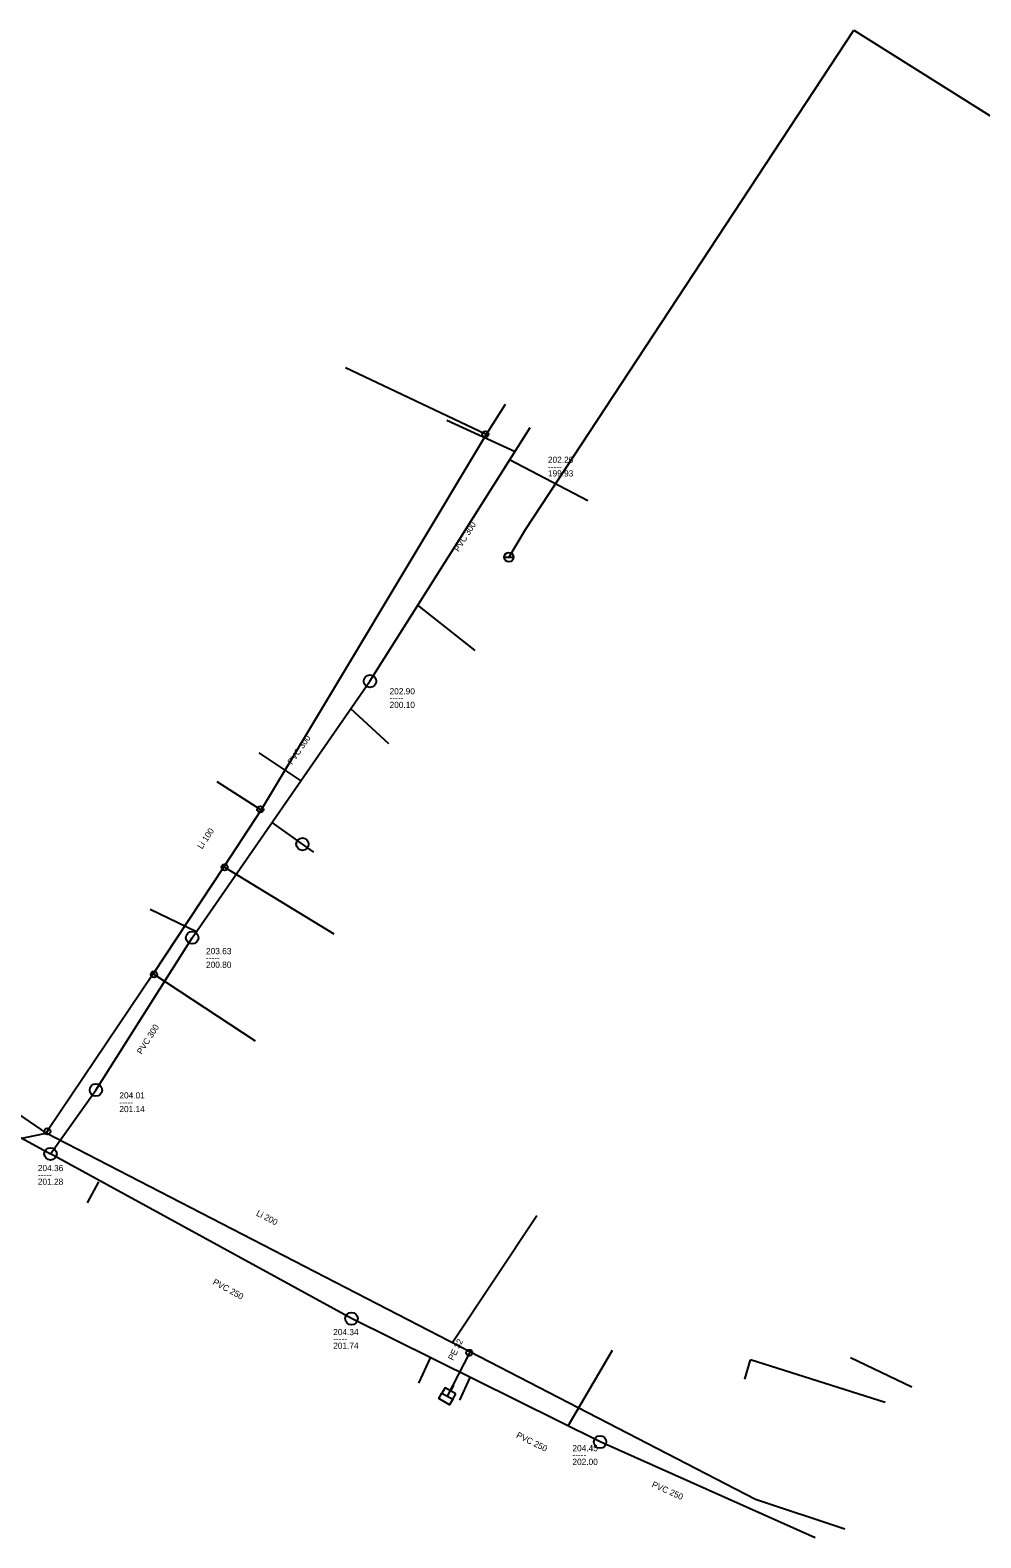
# Model space of a CAD drawing. Extents: x -695225 to -694112, y -1052622 to -1052029.
# Drawn here: x -694820.4 to -694667.2, y -1052494.8 to -1052251.9 of the extents above; entities that cross this region are included whole.
import ezdxf

# ---------------------------------------------------------------- set-up
doc = ezdxf.new("R2010")
doc.units = 0
doc.layers.add('Level 0', color=7, linetype='Continuous')

msp = doc.modelspace()

# ---------------------------------------------------------------- linework, layer by layer
at = {"layer": 'Level 0'}
for p, q in [((-694740.58, -1052332.34), (-694687.67, -1052251.87)), ((-694687.67, -1052251.87), (-694642.99, -1052280.01)), ((-694747.05, -1052316.98), (-694769.59, -1052306.28)), ((-694743.86, -1052312.18), (-694746.91, -1052317.04)), ((-694765.63, -1052356.77), (-694739.83, -1052315.88)), ((-694753.24, -1052314.74), (-694742.27, -1052319.76)), ((-694746.91, -1052317.04), (-694783.16, -1052377.52)), ((-694746.91, -1052317.04), (-694747.05, -1052316.98)), ((-694730.52, -1052327.74), (-694743.14, -1052321.13)), ((-694743.25, -1052336.86), (-694740.58, -1052332.34)), ((-694744, -1052336.8), (-694742.5, -1052336.8)), ((-694748.69, -1052351.82), (-694757.92, -1052344.55)), ((-694794.26, -1052398.11), (-694765.63, -1052356.77)), ((-694762.6, -1052366.87), (-694768.73, -1052361.24)), ((-694783.55, -1052368.32), (-694776.77, -1052372.86)), ((-694790.32, -1052372.96), (-694783.29, -1052377.44)), ((-694783.16, -1052377.52), (-694789.19, -1052386.69)), ((-694783.29, -1052377.44), (-694783.16, -1052377.52)), ((-694776.51, -1052383.04), (-694781.4, -1052379.54)), ((-694774.68, -1052384.34), (-694776.51, -1052383.04)), ((-694789.19, -1052386.69), (-694800.54, -1052403.94)), ((-694789.19, -1052386.69), (-694789.06, -1052386.77)), ((-694789.06, -1052386.77), (-694771.43, -1052397.47)), ((-694801.04, -1052393.49), (-694793.57, -1052397.11)), ((-694809.78, -1052422.66), (-694794.27, -1052398.11)), ((-694861.88, -1052399.44), (-694817.8, -1052429.59)), ((-694800.54, -1052403.94), (-694817.45, -1052429.07)), ((-694800.41, -1052404.02), (-694800.54, -1052403.94)), ((-694784.07, -1052414.79), (-694800.41, -1052404.02)), ((-694817.1, -1052432.95), (-694809.78, -1052422.66)), ((-694827.23, -1052427.44), (-694817.1, -1052432.95)), ((-694828.53, -1052431.86), (-694817.8, -1052429.59)), ((-694817.62, -1052429.32), (-694817.8, -1052429.59)), ((-694749.55, -1052464.87), (-694817.8, -1052429.59)), ((-694817.45, -1052429.07), (-694817.62, -1052429.32)), ((-694768.61, -1052459.5), (-694817.1, -1052432.95)), ((-694811.15, -1052440.82), (-694809.33, -1052437.46)), ((-694752.38, -1052463.41), (-694738.78, -1052442.87)), ((-694728.57, -1052479.37), (-694768.61, -1052459.5)), ((-694757.75, -1052469.88), (-694755.88, -1052465.82)), ((-694749.62, -1052465), (-694753.18, -1052472)), ((-694749.55, -1052464.87), (-694749.62, -1052465)), ((-694703.52, -1052488.66), (-694749.55, -1052464.87)), ((-694726.64, -1052464.65), (-694733.75, -1052476.8)), ((-694705.25, -1052469.23), (-694704.36, -1052466.15)), ((-694682.66, -1052473.03), (-694704.36, -1052466.15)), ((-694688.24, -1052465.76), (-694678.36, -1052470.5)), ((-694751.18, -1052472.66), (-694749.51, -1052468.97)), ((-694752.18, -1052470.26795), (-694752.68, -1052471.13397)), ((-694693.94, -1052494.82), (-694728.57, -1052479.37)), ((-694689.12, -1052493.4), (-694703.52, -1052488.66))]:
    msp.add_line(p, q, dxfattribs=at)
msp.add_lwpolyline([(-694752.31397, -1052472.5), (-694752.81397, -1052473.36603), (-694754.54603, -1052472.36603), (-694754.04603, -1052471.5)], dxfattribs=at)
msp.add_lwpolyline([(-694751.81397, -1052471.63397), (-694753.54603, -1052470.63397), (-694754.04603, -1052471.5), (-694752.31397, -1052472.5)], close=True, dxfattribs=at)
for centre, radius in [((-694747.05, -1052316.98), 0.5), ((-694743.25, -1052336.8), 0.75), ((-694765.63, -1052356.77), 1), ((-694783.29, -1052377.44), 0.5), ((-694776.51, -1052383.04), 1), ((-694789.06, -1052386.77), 0.5), ((-694794.27, -1052398.11), 1), ((-694800.41, -1052404.02), 0.5), ((-694809.78, -1052422.66), 1), ((-694817.62, -1052429.32), 0.5), ((-694817.1, -1052432.95), 1), ((-694768.61, -1052459.5), 1), ((-694749.62, -1052465), 0.5), ((-694728.57, -1052479.37), 1)]:
    msp.add_circle(centre, radius, dxfattribs=at)

# ---------------------------------------------------------------- texts
for s, p in [('202.26', (-694736.97, -1052321.59)), ('-----', (-694736.97, -1052322.69)), ('199.93', (-694736.97, -1052323.79)), ('-----', (-694762.48, -1052360)), ('202.90', (-694762.48, -1052358.9)), ('200.10', (-694762.48, -1052361.1)), ('203.63', (-694792.04, -1052400.77)), ('-----', (-694792.04, -1052401.87)), ('200.80', (-694792.04, -1052402.97)), ('-----', (-694806, -1052425.12)), ('204.01', (-694806, -1052424.02)), ('201.14', (-694806, -1052426.22)), ('204.36', (-694819.13, -1052435.73)), ('-----', (-694819.13, -1052436.83)), ('201.28', (-694819.13, -1052437.93)), ('204.34', (-694771.56, -1052462.16)), ('-----', (-694771.56, -1052463.26)), ('201.74', (-694771.56, -1052464.36)), ('204.45', (-694733.02, -1052480.87)), ('-----', (-694733.02, -1052481.97)), ('202.00', (-694733.02, -1052483.07))]:
    msp.add_text(s, height=1, dxfattribs=at).set_placement(p)
for s, rotation, p in [('PVC 300', 57.75, (-694751.35, -1052336.01)), ('PVC 300', 55.295, (-694778.18, -1052370.31)), ('Li 100', 56.672, (-694792.69, -1052383.92)), ('PVC 300', 57.716, (-694802.41, -1052417)), ('Li 200', 332.668, (-694784.06, -1052442.83)), ('PVC 250', 331.298, (-694791.05, -1052453.9)), ('PE 32', 63.043, (-694752.23, -1052466.33)), ('PVC 250', 333.607, (-694742.16, -1052478.6)), ('PVC 250', 335.956, (-694720.34, -1052486.57))]:
    msp.add_text(s, height=1, rotation=rotation, dxfattribs=at).set_placement(p)

doc.saveas('drawing.dxf')
